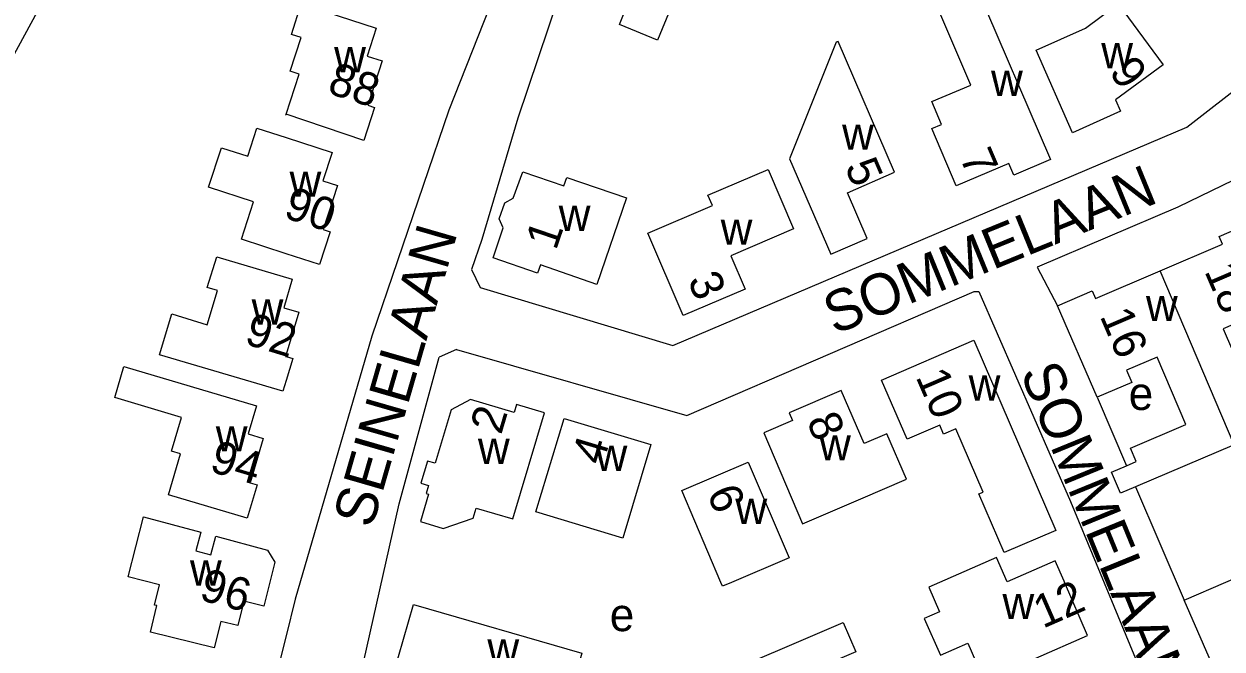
# Model space of a CAD drawing. Extents: x 157768 to 159790, y 387230 to 389604.
# Drawn here: x 158018.1 to 158163.8, y 388741.9 to 388817.9 of the extents above; entities that cross this region are included whole.
import ezdxf

# ---------------------------------------------------------------- set-up
doc = ezdxf.new("R2010")
doc.units = 0
for name, color, linetype in [('BLT_Basislijn', 7, 'Continuous'), ('BLT_Bebouwing', 7, 'Continuous'), ('BLT_Centroide', 7, 'Continuous'), ('BLT_Huisnummer', 7, 'Continuous'), ('BLT_Onderverdeling_panden', 7, 'Continuous'), ('BLT_Straatnaam', 7, 'Continuous')]:
    doc.layers.add(name, color=color, linetype=linetype)

msp = doc.modelspace()

# ---------------------------------------------------------------- linework, layer by layer
at = {"layer": 'BLT_Basislijn'}
for p, q in [((158072.55, 388788.06), (158073.61, 388785.86)), ((158073.61, 388785.86), (158097.01, 388778.81)), ((158070.72, 388778.32), (158068.59, 388777.39)), ((158148.59, 388772.51), (158152.17, 388764.18)), ((158153.27, 388761.62), (158159.2, 388747.85))]:
    msp.add_line(p, q, dxfattribs=at)
for points in [[(158141.34, 388872.65), (158134.87, 388869.35), (158092.1, 388842.36), (158088.08, 388835.85), (158078.17, 388806.44), (158073.8, 388791.69), (158072.55, 388788.06)], [(158082.41, 388839.45), (158069.8, 388807.44), (158060.42, 388779.94), (158051.12, 388747.97), (158050, 388743.49)], [(158097.01, 388778.81), (158159.52, 388805.38), (158181.5, 388822.51), (158185.18, 388825.67)], [(157999.6, 388714.31), (157996.35, 388733), (157991.67, 388750), (157987.48, 388761.14), (157984.33, 388774.78), (157996.61, 388786.34), (158005.72, 388797.58), (158014.57, 388809.95), (158022.62, 388824.69)], [(158166.92, 388800.3), (158165.19, 388798.92), (158158.43, 388795.64), (158141.3, 388788.35)], [(158141.3, 388788.35), (158143.8, 388783.64)], [(158070.72, 388778.32), (158098.73, 388770.31), (158133.64, 388785.38), (158134.2, 388785.38)], [(158134.2, 388785.38), (158145.35, 388759.84), (158157.86, 388729.66)], [(158051.59, 388691.65), (158053.73, 388707.69), (158057.87, 388733.42), (158063.73, 388759.54), (158068.59, 388777.39)], [(158050, 388743.49), (158046.41, 388729.18), (158042.63, 388705.92), (158041.23, 388694.28), (158041.05, 388690.74)]]:
    msp.add_lwpolyline(points, dxfattribs=at)
at = {"layer": 'BLT_Bebouwing'}
for p, q in [((158148.59, 388772.51), (158143.8, 388783.64)), ((158163.97, 388736.84), (158159.2, 388747.85))]:
    msp.add_line(p, q, dxfattribs=at)
for points in [[(158090.94, 388832.06), (158092.41, 388835.67), (158097.07, 388833.81), (158096.18, 388831.6), (158100.77, 388829.66), (158095.17, 388815.95), (158090.52, 388817.85), (158091.43, 388820.07), (158086.82, 388821.95), (158090.94, 388832.06)], [(158133.9, 388822.49), (158142.93, 388801.45), (158138.47, 388799.54), (158137.87, 388800.95), (158131.48, 388798.21), (158128.49, 388805.18), (158129.67, 388805.68), (158128.49, 388808.47), (158133.23, 388810.48), (158129, 388820.39), (158133.9, 388822.49)], [(158050, 388806.96), (158051.58, 388811.82), (158050.51, 388812.17), (158051.83, 388816.25), (158050.64, 388816.64), (158051.85, 388820.37), (158060.96, 388817.41), (158059.86, 388814.01), (158061.67, 388813.42), (158059.92, 388808.04), (158060.76, 388807.77), (158059.46, 388803.76), (158050, 388806.96)], [(158151.14, 388820.36), (158156.64, 388812.96), (158150.83, 388808.67), (158151.45, 388807.3), (158145.61, 388804.69), (158141.18, 388814.73), (158147.2, 388817.4), (158151.14, 388820.36)], [(158118.24, 388797.38), (158123.98, 388799.9), (158117.13, 388815.8), (158116.86, 388815.7), (158111.22, 388801.51), (158116.21, 388789.9), (158120.64, 388791.82), (158118.24, 388797.38)], [(158050, 388806.83), (158049.96, 388806.85), (158050, 388806.96)], [(158050, 388789.96), (158044.56, 388791.73), (158046.04, 388796.28), (158040.58, 388798.05), (158042.14, 388802.86), (158045.34, 388801.82), (158046.45, 388805.25), (158050, 388804.1)], [(158050, 388804.1), (158055.58, 388802.28), (158054.46, 388798.85), (158056.26, 388798.27), (158054.52, 388792.92), (158055.36, 388792.65), (158054.06, 388788.65), (158050, 388789.96)], [(158084.13, 388799.25), (158091.37, 388796.75), (158087.78, 388786.24), (158080.91, 388788.62), (158080.56, 388787.62), (158075.17, 388789.47), (158076.4, 388793.13), (158075.91, 388794.23), (158076.58, 388796.17), (158077.62, 388796.72), (158078.76, 388799.95), (158083.78, 388798.24), (158084.13, 388799.25)], [(158108.59, 388800.21), (158111.68, 388792.98), (158104.06, 388789.73), (158105.8, 388785.66), (158098.26, 388782.44), (158093.97, 388792.49), (158101.83, 388795.85), (158101.29, 388797.1), (158108.59, 388800.21)], [(158156.26, 388787.88), (158163.84, 388791.14), (158163.44, 388792.07), (158167.66, 388793.89), (158172.43, 388782.77), (158168.21, 388780.96), (158167.59, 388782.41), (158163.92, 388780.83), (158167.43, 388772.65), (158168.54, 388773.13), (158170.36, 388768.9), (158165.25, 388766.71)], [(158034.61, 388777.67), (158036.09, 388782.65), (158040.4, 388781.34), (158041.66, 388785.48), (158040.42, 388785.85), (158041.56, 388789.59), (158050.75, 388786.86)], [(158143.8, 388783.64), (158148, 388785.44), (158148.4, 388784.51), (158156.26, 388787.88)], [(158050.75, 388786.86), (158049.73, 388783.41)], [(158049.73, 388783.41), (158051.56, 388782.87), (158050, 388777.73)], [(158133.6, 388779.44), (158143.57, 388756.33), (158137.3, 388753.62), (158134.22, 388760.75), (158134.76, 388760.99), (158131.44, 388768.67), (158129.93, 388768.02), (158129.46, 388769.13), (158125.51, 388767.42), (158122.4, 388774.61), (158133.6, 388779.44)], [(158050, 388774.57), (158049.59, 388773.24), (158034.61, 388777.67)], [(158050, 388777.73), (158049.93, 388777.49), (158050, 388777.47)], [(158050, 388777.47), (158050.81, 388777.23), (158050, 388774.57)], [(158152.67, 388766.31), (158159.39, 388769.2), (158155.88, 388777.38), (158152.18, 388775.79), (158152.82, 388774.32), (158148.59, 388772.51)], [(158030.28, 388776.24), (158046.41, 388771.48), (158045.39, 388768.05), (158047.23, 388767.5), (158045.62, 388762.11), (158046.49, 388761.85), (158045.28, 388757.8), (158035.7, 388760.66), (158037.18, 388765.62), (158036.06, 388765.95), (158037.29, 388770.06), (158029.17, 388772.49), (158030.28, 388776.24)], [(158120.28, 388766.89), (158117.5, 388773.35), (158111.16, 388770.62), (158111.56, 388769.67), (158108.08, 388768.18), (158112.8, 388757.13), (158119.89, 388760.18), (158125.41, 388762.55), (158123.03, 388768.07), (158120.28, 388766.89)], [(158066.38, 388762.07), (158067.32, 388761.79), (158067.04, 388760.83), (158067.32, 388760.74), (158066.33, 388757.39), (158069.09, 388756.57), (158072.75, 388757.82), (158073.12, 388759.03), (158077.58, 388757.71), (158081.4, 388770.64), (158078, 388771.65), (158077.72, 388770.68), (158072.41, 388772.26), (158070.05, 388770.98), (158068.11, 388764.48), (158067.18, 388764.75), (158066.38, 388762.07)], [(158080.37, 388758.57), (158083.8, 388769.92), (158094.33, 388766.77), (158090.92, 388755.39), (158080.37, 388758.57)], [(158152.17, 388764.18), (158153.36, 388764.7), (158152.67, 388766.31)], [(158165.25, 388766.71), (158153.27, 388761.62)], [(158104.15, 388750), (158103.07, 388749.54), (158102.87, 388750), (158098.1, 388761.16), (158106.19, 388764.63), (158111.16, 388753), (158104.15, 388750)], [(158150.35, 388763.4), (158152.17, 388764.18)], [(158153.27, 388761.62), (158151.46, 388760.84), (158150.35, 388763.4)], [(158144.59, 388750.13), (158143.5, 388752.64), (158137.65, 388750.08), (158136.36, 388753.04), (158129.42, 388750), (158128.12, 388749.43), (158129.44, 388746.42), (158127.59, 388745.61), (158129.54, 388741.14), (158132.88, 388742.6), (158134.88, 388738.03), (158147.43, 388743.52), (158144.63, 388750.03), (158144.59, 388750.13)], [(158159.2, 388747.85), (158169.3, 388752.2)], [(158062.45, 388736.76), (158065.48, 388747.29), (158085.95, 388741.39), (158084.6, 388736.75), (158073.57, 388739.96), (158071.85, 388734.04), (158062.45, 388736.76)], [(158105.48, 388739.88), (158110.07, 388741.85), (158117.74, 388745.14), (158119.27, 388741.57), (158111.6, 388738.28), (158115.86, 388728.37), (158114.94, 388727.98), (158116.22, 388724.99), (158123.97, 388728.32), (158125.45, 388724.89), (158125.96, 388723.69)]]:
    msp.add_lwpolyline(points, dxfattribs=at)
msp.add_lwpolyline([(158032.65, 388757.98), (158039.64, 388756.1), (158039.04, 388753.84), (158040.85, 388753.36), (158041.46, 388755.61), (158047.75, 388753.92), (158048.62, 388752.44), (158047.29, 388747.11), (158044.86, 388747.72), (158044.12, 388744.74), (158042.08, 388745.25), (158041.27, 388742.03), (158033.5, 388743.96), (158034.3, 388747.17), (158034.01, 388747.24), (158034.62, 388749.72), (158030.8, 388750.68)], close=True, dxfattribs=at)
at = {"layer": 'BLT_Onderverdeling_panden'}
msp.add_line((158165.25, 388766.71), (158156.26, 388787.88), dxfattribs=at)

# ---------------------------------------------------------------- texts
at = {"layer": 'BLT_Centroide'}
for s, p in [('w', (158149.1, 388812.53)), ('w', (158055.84, 388812.03)), ('w', (158135.7, 388809.16)), ('w', (158117.59, 388802.61)), ('w', (158050.42, 388796.89)), ('w', (158083.14, 388792.75)), ('w', (158102.83, 388791.06)), ('w', (158154.53, 388781.77)), ('w', (158045.81, 388781.36)), ('w', (158132.98, 388772.12)), ('e', (158152.44, 388770.97)), ('w', (158041.45, 388765.92)), ('w', (158073.32, 388764.41)), ('w', (158114.8, 388764.83)), ('w', (158087.62, 388763.56)), ('w', (158104.62, 388757.09)), ('w', (158038.31, 388749.62)), ('w', (158137.09, 388745.53)), ('e', (158089.35, 388744.07)), ('w', (158074.47, 388740))]:
    msp.add_text(s, height=4, dxfattribs=at).set_placement(p)
at = {"layer": 'BLT_Huisnummer'}
for s, rotation, p in [('9', 306.6002, (158149.95, 388812.05)), ('88', 342.0222, (158054.87, 388809.55)), ('7', 293.2115, (158131.84, 388801.73)), ('5', 293.2652, (158117.87, 388800.56)), ('90', 342.0222, (158049.55, 388794.41)), ('1', 71.1164, (158082.8, 388790.28)), ('3', 293.1181, (158098.77, 388786.76)), ('18', 293.2578, (158161.6, 388787.86)), ('16', 293.2576, (158148.88, 388782.4)), ('92', 343.0613, (158044.79, 388779.05)), ('10', 293.383, (158126.5, 388775.01)), ('2', 73.53, (158076.14, 388767.86)), ('8', 293.1101, (158113.23, 388769.65)), ('94', 343.3392, (158040.55, 388763.54)), ('4', 73.3051, (158088.49, 388764.14)), ('6', 293.1428, (158101.1, 388760.84)), ('96', 344.9454, (158039.3, 388747.91)), ('12', 23.6291, (158142, 388744.35))]:
    msp.add_text(s, height=4, rotation=rotation, dxfattribs=at).set_placement(p)
at = {"layer": 'BLT_Straatnaam'}
for s, rotation, p in [('SOMMELAAN', 22.2486, (158116.66, 388780.09)), ('SEINELAAN', 73.8793, (158060.44, 388756.45)), ('SOMMELAAN', 292.2486, (158139.2, 388775.54))]:
    msp.add_text(s, height=5, rotation=rotation, dxfattribs=at).set_placement(p)

doc.saveas('drawing.dxf')
